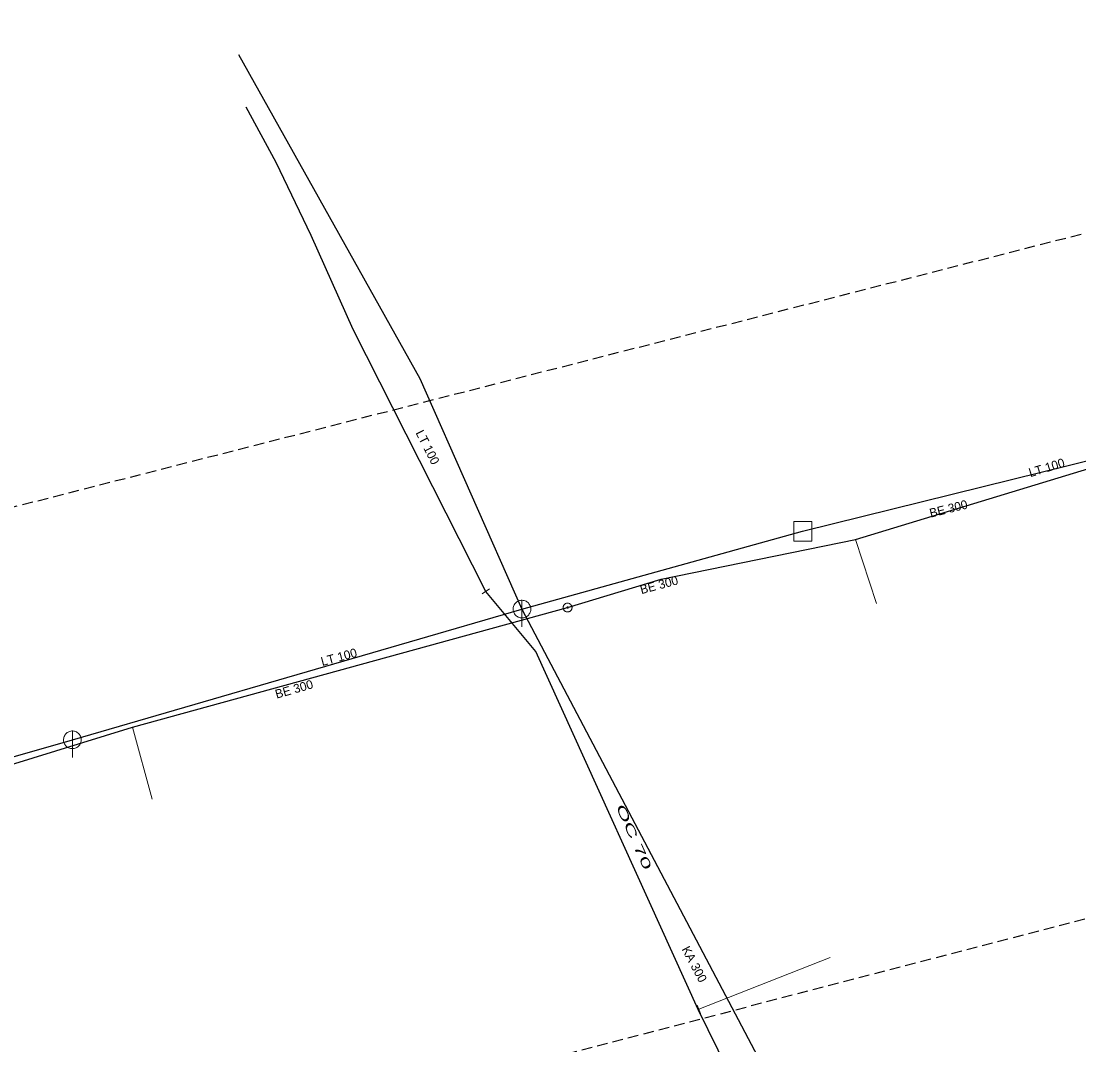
# Model space of a CAD drawing. Extents: x -690254 to -689100, y -975264 to -974703.
# Drawn here: x -689341.6 to -689222, y -974879.5 to -974763.7 of the extents above; entities that cross this region are included whole.
import ezdxf

# ---------------------------------------------------------------- set-up
doc = ezdxf.new("R2010")
doc.units = 0
doc.header["$LTSCALE"] = 0.4
doc.linetypes.add('MEDIUM_DASHED', pattern=[4.5, 3, -1.5])
for name, color, linetype, lineweight in [('1', 7, 'Continuous', 13), ('13', 7, 'Continuous', 13), ('14', 7, 'Continuous', 13), ('17', 7, 'Continuous', 25), ('22', 7, 'Continuous', 13), ('34', 7, 'Continuous', 13), ('47', 7, 'Continuous', 13), ('63', 7, 'MEDIUM_DASHED', 25)]:
    doc.layers.add(name, color=color, linetype=linetype, lineweight=lineweight)

msp = doc.modelspace()

# ---------------------------------------------------------------- linework, layer by layer
at = {"layer": '13'}
for p, q in [((-689247.23, -974822.281), (-689244.864, -974829.539)), ((-689328.987, -974843.539), (-689326.783, -974851.682)), ((-689264.948, -974875.438), (-689250.087, -974869.585))]:
    msp.add_line(p, q, dxfattribs=at)
at = {"layer": '14', "lineweight": 25}
for p, q in [((-689253.213, -974821.367), (-689219.366, -974812.992)), ((-689284.956, -974830.167), (-689242.595, -974910.571))]:
    msp.add_line(p, q, dxfattribs=at)
at = {"layer": '14'}
msp.add_line((-689265.046, -974875.476), (-689264.948, -974875.438), dxfattribs=at)
at = {"layer": '14', "lineweight": 25}
for points in [[(-689317.019, -974767.434), (-689296.506, -974804.077), (-689284.956, -974830.167)], [(-689390.66, -974860.629), (-689385.349, -974859.182), (-689369.98, -974854.739), (-689335.804, -974844.955), (-689284.956, -974830.167), (-689253.213, -974821.367)]]:
    msp.add_lwpolyline(points, dxfattribs=at)
at = {"layer": '17'}
for points in [[(-689289.051, -974828.161), (-689304.03, -974798.539), (-689308.791, -974787.916), (-689312.738, -974779.652), (-689316.141, -974773.388)], [(-689279.795, -974829.994), (-689269.201, -974826.793), (-689247.23, -974822.281), (-689201.373, -974808.357), (-689174.12, -974806.199)], [(-689248.919, -974908.281), (-689255.973, -974893.858), (-689265.046, -974875.476), (-689283.401, -974834.953), (-689289.051, -974828.161)], [(-689358.632, -974852.602), (-689352.123, -974850.624), (-689348.96, -974849.653), (-689328.987, -974843.539), (-689279.795, -974829.994)]]:
    msp.add_lwpolyline(points, dxfattribs=at)
at = {"layer": '22'}
for p, q in [((-689284.957, -974832.167), (-689284.956, -974829.167)), ((-689335.804, -974846.955), (-689335.803, -974843.955))]:
    msp.add_line(p, q, dxfattribs=at)
for points in [[(-689254.193, -974820.277), (-689252.16, -974820.277), (-689252.16, -974822.47), (-689254.193, -974822.47)], [(-689283.957, -974830.167), (-689283.962, -974830.058), (-689283.98, -974829.95), (-689284.01, -974829.844), (-689284.05, -974829.743), (-689284.102, -974829.646), (-689284.164, -974829.556), (-689284.236, -974829.473), (-689284.316, -974829.399), (-689284.404, -974829.333), (-689284.498, -974829.278), (-689284.598, -974829.233), (-689284.703, -974829.2), (-689284.81, -974829.178), (-689284.919, -974829.168), (-689285.029, -974829.17), (-689285.137, -974829.184), (-689285.244, -974829.209), (-689285.347, -974829.246), (-689285.445, -974829.295), (-689285.537, -974829.353), (-689285.623, -974829.422), (-689285.7, -974829.499), (-689285.769, -974829.585), (-689285.828, -974829.677), (-689285.876, -974829.775), (-689285.913, -974829.878), (-689285.939, -974829.985), (-689285.953, -974830.093), (-689285.956, -974830.203), (-689285.946, -974830.312), (-689285.925, -974830.419), (-689285.891, -974830.523), (-689285.847, -974830.623), (-689285.792, -974830.718), (-689285.726, -974830.806), (-689285.652, -974830.886), (-689285.569, -974830.958), (-689285.479, -974831.02), (-689285.383, -974831.072), (-689285.281, -974831.113), (-689285.176, -974831.143), (-689285.068, -974831.161), (-689284.958, -974831.167), (-689284.849, -974831.161), (-689284.741, -974831.143), (-689284.636, -974831.114), (-689284.534, -974831.073), (-689284.437, -974831.021), (-689284.347, -974830.959), (-689284.264, -974830.888), (-689284.189, -974830.808), (-689284.124, -974830.72), (-689284.068, -974830.626), (-689284.024, -974830.526), (-689283.99, -974830.422), (-689283.968, -974830.314), (-689283.958, -974830.205)], [(-689334.804, -974844.955), (-689334.809, -974844.846), (-689334.827, -974844.738), (-689334.857, -974844.632), (-689334.897, -974844.531), (-689334.949, -974844.434), (-689335.011, -974844.344), (-689335.083, -974844.261), (-689335.163, -974844.187), (-689335.251, -974844.121), (-689335.345, -974844.066), (-689335.445, -974844.021), (-689335.55, -974843.988), (-689335.657, -974843.966), (-689335.766, -974843.956), (-689335.876, -974843.958), (-689335.984, -974843.972), (-689336.091, -974843.997), (-689336.194, -974844.034), (-689336.292, -974844.083), (-689336.384, -974844.141), (-689336.47, -974844.21), (-689336.547, -974844.287), (-689336.616, -974844.373), (-689336.675, -974844.465), (-689336.723, -974844.563), (-689336.76, -974844.666), (-689336.786, -974844.773), (-689336.8, -974844.881), (-689336.803, -974844.991), (-689336.793, -974845.1), (-689336.772, -974845.207), (-689336.738, -974845.311), (-689336.694, -974845.411), (-689336.639, -974845.506), (-689336.573, -974845.594), (-689336.499, -974845.674), (-689336.416, -974845.746), (-689336.326, -974845.808), (-689336.23, -974845.86), (-689336.128, -974845.901), (-689336.023, -974845.931), (-689335.915, -974845.949), (-689335.805, -974845.955), (-689335.696, -974845.949), (-689335.588, -974845.931), (-689335.483, -974845.902), (-689335.381, -974845.861), (-689335.284, -974845.809), (-689335.194, -974845.747), (-689335.111, -974845.676), (-689335.036, -974845.596), (-689334.971, -974845.508), (-689334.915, -974845.414), (-689334.871, -974845.314), (-689334.837, -974845.21), (-689334.815, -974845.102), (-689334.805, -974844.993)]]:
    msp.add_lwpolyline(points, close=True, dxfattribs=at)
at = {"layer": '34'}
for p, q in [((-689288.627, -974827.894), (-689289.474, -974828.426)), ((-689265.128, -974874.971), (-689264.768, -974875.904))]:
    msp.add_line(p, q, dxfattribs=at)
at = {"layer": '47'}
for points in [[(-689279.559, -974830.435), (-689279.515, -974830.408), (-689279.473, -974830.376), (-689279.435, -974830.34), (-689279.4, -974830.301), (-689279.37, -974830.258), (-689279.345, -974830.212), (-689279.325, -974830.164), (-689279.31, -974830.114), (-689279.3, -974830.063), (-689279.295, -974830.011), (-689279.296, -974829.958), (-689279.303, -974829.906), (-689279.314, -974829.855), (-689279.331, -974829.806), (-689279.353, -974829.758), (-689279.38, -974829.714), (-689279.412, -974829.672), (-689279.448, -974829.633), (-689279.487, -974829.599), (-689279.53, -974829.569), (-689279.576, -974829.544), (-689279.625, -974829.523), (-689279.675, -974829.508), (-689279.725, -974829.498), (-689279.777, -974829.494), (-689279.83, -974829.495), (-689279.882, -974829.501), (-689279.933, -974829.513), (-689279.982, -974829.53), (-689280.03, -974829.552), (-689280.074, -974829.579), (-689280.116, -974829.611), (-689280.155, -974829.646), (-689280.189, -974829.686), (-689280.219, -974829.729), (-689280.244, -974829.774), (-689280.265, -974829.823), (-689280.28, -974829.873), (-689280.29, -974829.924), (-689280.294, -974829.976), (-689280.293, -974830.029), (-689280.287, -974830.08), (-689280.275, -974830.132), (-689280.258, -974830.181), (-689280.236, -974830.229), (-689280.209, -974830.273), (-689280.177, -974830.315), (-689280.142, -974830.353), (-689280.102, -974830.388), (-689280.059, -974830.418), (-689280.014, -974830.443), (-689279.966, -974830.463), (-689279.916, -974830.478), (-689279.864, -974830.488), (-689279.812, -974830.493), (-689279.759, -974830.492), (-689279.708, -974830.486), (-689279.656, -974830.474), (-689279.607, -974830.457)], [(-689279.756, -974830.066), (-689279.748, -974830.062), (-689279.742, -974830.056), (-689279.736, -974830.051), (-689279.73, -974830.044), (-689279.725, -974830.037), (-689279.721, -974830.029), (-689279.717, -974830.021), (-689279.715, -974830.013), (-689279.714, -974830.005), (-689279.713, -974829.996), (-689279.713, -974829.987), (-689279.714, -974829.979), (-689279.716, -974829.971), (-689279.718, -974829.963), (-689279.722, -974829.955), (-689279.726, -974829.947), (-689279.732, -974829.941), (-689279.737, -974829.935), (-689279.744, -974829.929), (-689279.751, -974829.924), (-689279.759, -974829.92), (-689279.767, -974829.916), (-689279.775, -974829.914), (-689279.784, -974829.912), (-689279.792, -974829.912), (-689279.801, -974829.912), (-689279.809, -974829.913), (-689279.817, -974829.915), (-689279.825, -974829.917), (-689279.833, -974829.921), (-689279.841, -974829.925), (-689279.847, -974829.931), (-689279.853, -974829.936), (-689279.859, -974829.943), (-689279.864, -974829.95), (-689279.868, -974829.957), (-689279.872, -974829.966), (-689279.874, -974829.974), (-689279.876, -974829.983), (-689279.876, -974829.991), (-689279.876, -974830), (-689279.875, -974830.008), (-689279.873, -974830.016), (-689279.871, -974830.024), (-689279.867, -974830.032), (-689279.863, -974830.04), (-689279.857, -974830.046), (-689279.852, -974830.052), (-689279.845, -974830.058), (-689279.838, -974830.063), (-689279.831, -974830.067), (-689279.822, -974830.071), (-689279.814, -974830.073), (-689279.806, -974830.074), (-689279.797, -974830.075), (-689279.788, -974830.075), (-689279.78, -974830.074), (-689279.772, -974830.072), (-689279.764, -974830.07)]]:
    msp.add_lwpolyline(points, close=True, dxfattribs=at)
at = {"layer": '63'}
msp.add_lwpolyline([(-690175.832, -975238.167), (-690201.511, -975156.663), (-690201.511, -975156.663), (-689696.859, -975008.171), (-689696.859, -975008.171), (-689730.354, -974917.735), (-689730.354, -974917.735), (-689127.452, -974763.66), (-689127.452, -974763.66), (-689118.52, -974838.465), (-689118.52, -974838.465), (-689624.288, -974970.21), (-689624.288, -974970.21), (-689593.026, -975070.694), (-689593.026, -975070.694)], close=True, dxfattribs=at)

# ---------------------------------------------------------------- texts
at = {"layer": '1'}
for s, rotation, p in [('LT 100', 297, (-689297.015, -974810.228)), ('LT 100', 17, (-689227.458, -974815.247)), ('BE 300', 14, (-689238.724, -974819.826)), ('BE 300', 15, (-689271.445, -974828.481)), ('LT 100', 15, (-689307.544, -974836.612)), ('BE 300', 16, (-689312.706, -974840.304)), ('KA 300', 298, (-689266.93, -974868.639))]:
    msp.add_text(s, height=1, rotation=rotation, dxfattribs=at).set_placement(p)
at = {"layer": '1', "width": 2.05}
msp.add_text('OC 70 ', height=1, rotation=294, dxfattribs=at).set_placement((-689274.358, -974852.53))

doc.saveas('drawing.dxf')
